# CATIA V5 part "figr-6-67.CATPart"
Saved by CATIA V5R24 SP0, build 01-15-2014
Part number: Part2
Bounding box of the stored display mesh (mm): x -31.464 to 31.464, y -26.321 to 36.69, z 59.463 to 122.391
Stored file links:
  D:\KAVITA\CATIA V5-6R2014 Project_ Kavita\CATIA V5-6R2014_partfiles\Partfiles\c06_catia_v5-6r2014_prt\figr-6-67.CATPart
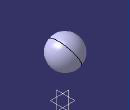
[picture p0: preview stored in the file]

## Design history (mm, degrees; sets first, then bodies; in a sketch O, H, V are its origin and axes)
Body1 (main body)
  Sketch1 on yz-plane, origin (0, 0, 0), H (0, 1, 0), V (0, 0, 1)
    axis line L1 (-55.8323, 90.9269) -> (61.0167, 90.9269)
    arc A1 centre (5.1844, 90.9269) radius 31.5054 from (36.6898, 90.9269) to (-26.3209, 90.9269) ccw
    point P3 (5.1844, 90.9269)
    point P4 (36.6898, 90.9269)
    point P5 (-26.3209, 90.9269)
    line L2 (-26.3209, 90.9269) -> (36.6898, 90.9269)
    horizontal: L1 H, L2 H
    coincidence: P3 L1, P4 L1, P5 L1
  Shaft1: profile Sketch1, axis Sketch1.L1, angle 360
